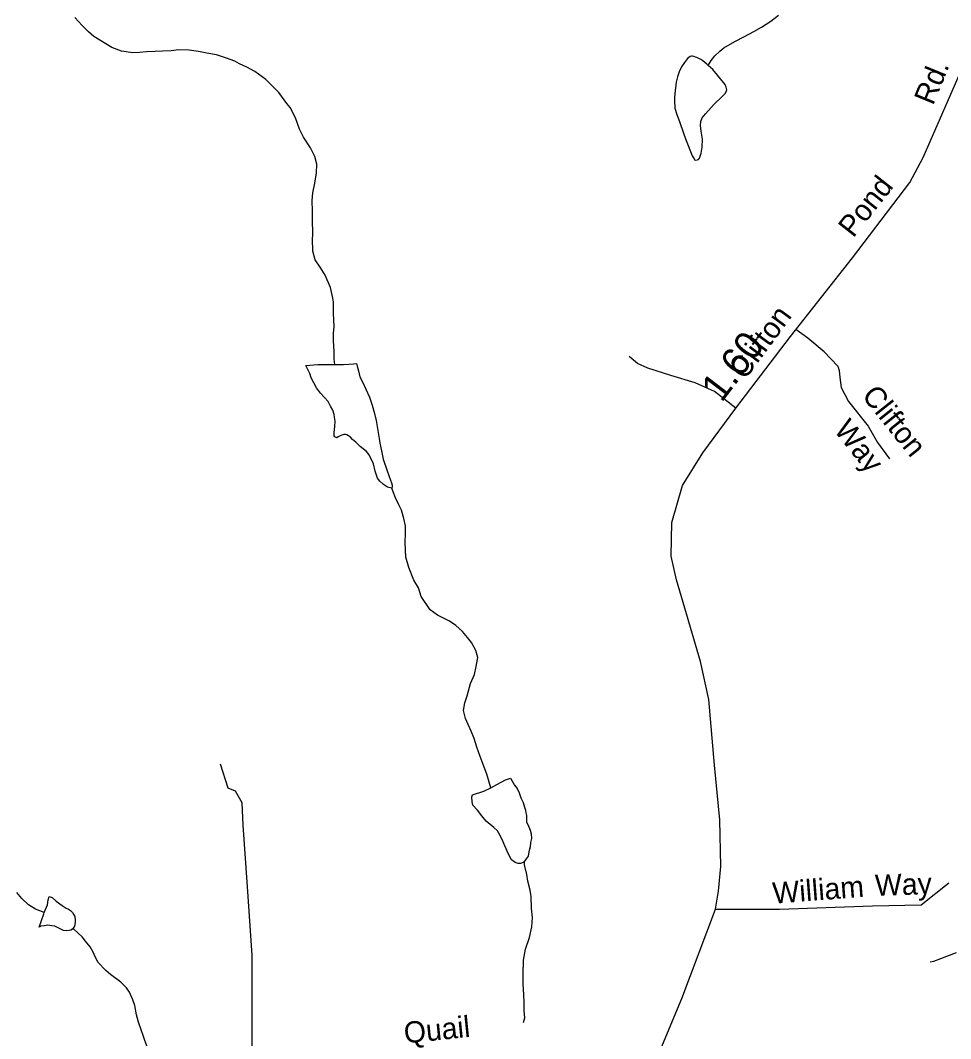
# Model space of a CAD drawing. Extents: x 2126262 to 2293712, y 749403 to 919119.
# Drawn here: x 2189866 to 2194027, y 811845 to 816398 of the extents above; entities that cross this region are included whole.
import ezdxf

# ---------------------------------------------------------------- set-up
doc = ezdxf.new("R2010")
doc.units = 0
for name, color, linetype in [('Exist Hydrographic Misc Water Feature', 7, 'Continuous'), ('Exist Road Non-System Type 51', 7, 'Continuous'), ('Exist Road Non-System Type 51 Label', 7, 'Continuous'), ('Exist Road Secondary Mileage Hundredths English Label', 7, 'Continuous'), ('Exist Road Secondary Type 51 Attributed', 7, 'Continuous'), ('Exist Road Secondary Type 51 Label', 7, 'Continuous')]:
    doc.layers.add(name, color=color, linetype=linetype)

msp = doc.modelspace()

# ---------------------------------------------------------------- linework, layer by layer
at = {"layer": 'Exist Hydrographic Misc Water Feature'}
for points in [[(2191271.9, 814859.4), (2191269.8, 814883.4), (2191269.6, 814919.4), (2191267.1, 814965.4), (2191266.7, 814999.4), (2191268.8, 815027.4), (2191266.3, 815089.3), (2191266.1, 815139.3), (2191261.8, 815163.3), (2191253.6, 815203.2), (2191229, 815259), (2191206.9, 815294.8), (2191184.9, 815326.7), (2191174.3, 815366.6), (2191172, 815420.6), (2191174.1, 815438.6), (2191173.2, 815512.6), (2191173.2, 815520.6), (2191173.2, 815544.5), (2191170.8, 815592.5), (2191174.7, 815626.5), (2191182.3, 815670.6), (2191190, 815716.6), (2191191.9, 815754.6), (2191183.5, 815788.5), (2191163.4, 815828.4), (2191133, 815876.1), (2191114.8, 815912), (2191096.3, 815961.9), (2191072.1, 816007.7), (2191058, 816025.6), (2191021.5, 816075.4), (2190963.3, 816132.9), (2190915.1, 816168.6), (2190878.8, 816188.3), (2190846.8, 816204.1), (2190824.9, 816216), (2190788.6, 816229.7), (2190742.6, 816243.4), (2190700.6, 816251.1), (2190662.7, 816258.8), (2190620.6, 816264.5), (2190574.5, 816266.2), (2190540.6, 816262), (2190502.5, 816259.7), (2190468.7, 816259.5), (2190430.5, 816257.2), (2190398.5, 816255), (2190368.6, 816252.8), (2190318.6, 816260.5), (2190274.5, 816276.2), (2190194.1, 816325.6), (2190170.1, 816347.4), (2190141.8, 816375.2), (2190109.6, 816411)], [(2192942, 816196.5), (2192956.2, 816218.6), (2192971.7, 816238.7), (2192993.9, 816260.8), (2193011.5, 816274.9), (2193061.4, 816303.3), (2193105.2, 816325.6), (2193147.1, 816347.9), (2193180.9, 816368.1), (2193222.7, 816394.4), (2193256.6, 816420.6)], [(2192942, 816196.5), (2192936.1, 816202.4), (2192918, 816216.3), (2192910, 816222.3), (2192900, 816228.2), (2192892, 816232.1), (2192885.8, 816234.1), (2192877.8, 816236.1), (2192871.9, 816238), (2192867.8, 816238), (2192861.8, 816235.9), (2192856.1, 816231.9), (2192850.2, 816227.9), (2192836, 816209.7), (2192822.3, 816189.7), (2192812.4, 816167.6), (2192804.6, 816145.5), (2192798.9, 816121.5), (2192793.1, 816069.5), (2192791.3, 816053.5), (2192791.3, 816039.5), (2192793.6, 816005.5), (2192801.8, 815977.6), (2192813.9, 815945.7), (2192832.3, 815893.8), (2192840.5, 815867.9), (2192852.6, 815838), (2192871.1, 815792.1), (2192879.1, 815778.2), (2192881.1, 815774.2), (2192887.1, 815772.2), (2192899.2, 815776.3), (2192903.1, 815782.3), (2192910.8, 815804.4), (2192914.7, 815830.4), (2192916.6, 815866.4), (2192910.2, 815902.3), (2192908.2, 815928.3), (2192909.8, 815946.4), (2192915.8, 815962.4), (2192929.5, 815980.5), (2192969.3, 816022.8), (2193005.2, 816057), (2193019.1, 816073), (2193024.9, 816087.1), (2193022.8, 816099.1), (2193018.9, 816111), (2192962.3, 816178.6), (2192942, 816196.5)], [(2191527.6, 814305.4), (2191507.5, 814311.2), (2191489.6, 814323.1), (2191473.2, 814337), (2191463.4, 814350.9), (2191453.1, 814382.8), (2191444.7, 814414.7), (2191426.5, 814454.6), (2191414.6, 814470.5), (2191386.3, 814492.3), (2191378.3, 814500.2), (2191366.4, 814512.2), (2191352, 814524.1), (2191342, 814534), (2191334, 814539.9), (2191326, 814543.9), (2191320.1, 814545.9), (2191312.1, 814545.8), (2191304.1, 814543.8), (2191296.1, 814539.7), (2191288.1, 814535.6), (2191282.1, 814531.6), (2191272.1, 814535.5), (2191270, 814539.5), (2191270, 814555.5), (2191271.9, 814581.5), (2191273.5, 814605.5), (2191271.7, 814623.5), (2191269.4, 814635.5), (2191263.3, 814655.5), (2191253, 814673.4), (2191243.2, 814693.3), (2191226.8, 814711.2), (2191208.9, 814731.1), (2191190.7, 814754.9), (2191166.3, 814798.8), (2191160.3, 814818.7), (2191152.1, 814836.6), (2191142.1, 814854.6), (2191195.8, 814858.9), (2191263.9, 814859.4), (2191271.9, 814859.4)], [(2191271.9, 814859.4), (2191311.8, 814859.7), (2191335.8, 814859.9), (2191355.7, 814862), (2191369.9, 814864.2), (2191371.7, 814852.1), (2191378.1, 814830.2), (2191384.2, 814804.2), (2191398.4, 814778.3), (2191410.5, 814748.5), (2191426.9, 814712.6), (2191439, 814676.6), (2191449.2, 814640.7), (2191457.6, 814608.8), (2191470.1, 814528.9), (2191474.3, 814507), (2191480.6, 814473), (2191488.8, 814435.1), (2191507.1, 814383.2), (2191521.4, 814341.3), (2191525.5, 814329.3), (2191529.6, 814319.4), (2191529.6, 814313.4), (2191527.6, 814305.4)], [(2191970.5, 812966.8), (2191952.2, 813026.7), (2191936, 813070.6), (2191921.9, 813106.5), (2191907.3, 813148.3), (2191895, 813186.2), (2191882.7, 813220.1), (2191868.8, 813250), (2191856.5, 813275.9), (2191848.3, 813311.9), (2191854, 813346), (2191863.8, 813377.9), (2191879.6, 813432.1), (2191897.3, 813472.2), (2191905.1, 813508.2), (2191912.7, 813548.2), (2191902.6, 813580.2), (2191884.4, 813616), (2191866.1, 813637.9), (2191843.8, 813665.7), (2191813.8, 813691.5), (2191785.5, 813711.3), (2191761.5, 813723.2), (2191731.4, 813738.9), (2191699.4, 813762.7), (2191658.8, 813822.4), (2191646.5, 813860.3), (2191626.4, 813894.2), (2191604, 813952), (2191589.9, 813997.9), (2191587.2, 814061.9), (2191589.1, 814103.9), (2191588.9, 814137.8), (2191580.5, 814169.8), (2191570.2, 814207.7), (2191558.1, 814231.6), (2191543.8, 814263.5), (2191533.7, 814289.4), (2191527.6, 814305.4)], [(2191970.5, 812966.8), (2191996.5, 812981), (2192036.3, 813001.3), (2192058.2, 813009.4), (2192076.5, 812977.5), (2192088.6, 812963.6), (2192096.8, 812943.7), (2192104.8, 812921.8), (2192115, 812899.9), (2192121.4, 812879.9), (2192125.3, 812865.9), (2192127.3, 812853.9), (2192129.6, 812841.9), (2192129.6, 812822), (2192129.6, 812814), (2192139.8, 812792.1), (2192145.8, 812776.1), (2192150.1, 812760.1), (2192152.2, 812740.1), (2192148.3, 812722.1), (2192146.2, 812702.1), (2192140.5, 812680.1), (2192136.8, 812660.1), (2192128.8, 812648), (2192120.8, 812638)], [(2192120.8, 812638), (2192114.8, 812631.9), (2192102.7, 812627.9), (2192092.9, 812627.8), (2192078.7, 812631.7), (2192062.8, 812643.6), (2192048.6, 812669.4), (2192032.4, 812707.3), (2192020.3, 812735.3), (2192006.2, 812763.1), (2192000, 812773.1), (2191983.8, 812789), (2191949.6, 812816.7), (2191929.5, 812840.6), (2191911.2, 812866.4), (2191889.3, 812888.3), (2191887, 812904.2), (2191885, 812926.2), (2191888.9, 812934.3), (2191938.9, 812950.6), (2191970.5, 812966.8)], [(2192115.9, 811916.2), (2192121.6, 811938.2), (2192119.5, 811970.2), (2192119.1, 812008.1), (2192117.1, 812040.1), (2192114.6, 812090.1), (2192114.2, 812132), (2192115.9, 812196), (2192125.5, 812244.1), (2192143.3, 812296.2), (2192152.8, 812344.3), (2192156.5, 812386.3), (2192152.4, 812428.2), (2192149.9, 812480.2), (2192145.8, 812508.2), (2192135.5, 812548.1), (2192131.2, 812578), (2192121, 812622), (2192120.8, 812638)], [(2189973.1, 812409.3), (2189933.1, 812423), (2189902.7, 812442.8), (2189872.8, 812470.5), (2189850.6, 812498.4)], [(2189973.1, 812409.3), (2189986.8, 812443.3), (2189990.9, 812465.4), (2189994.6, 812479.4), (2190008.5, 812475.5), (2190026.8, 812459.6), (2190052.8, 812439.8), (2190071.1, 812427.9), (2190081.1, 812424), (2190091, 812418.1), (2190099, 812408.2), (2190105.1, 812398.2), (2190109.2, 812390.2), (2190111.3, 812374.2), (2190111.3, 812364.2), (2190107.6, 812348.2), (2190101.6, 812338.2)], [(2190101.6, 812338.2), (2190099.6, 812334.2), (2190091.6, 812330.1), (2190083.6, 812328), (2190073.5, 812326), (2190059.6, 812327.9), (2190035.6, 812339.7), (2190019.6, 812347.6), (2190007.5, 812349.5), (2189989.5, 812351.4), (2189973.5, 812349.3), (2189957.5, 812347.1), (2189949.5, 812343.2), (2189971, 812403.3), (2189973.1, 812409.3)], [(2190455.8, 811720.8), (2190445.5, 811754.7), (2190439.4, 811778.6), (2190431.2, 811812.6), (2190422.7, 811836.5), (2190416.8, 811854.5), (2190406.5, 811884.4), (2190394.2, 811918.3), (2190386, 811950.3), (2190377.8, 811992.2), (2190369.6, 812018.1), (2190353.6, 812052), (2190341.3, 812071.9), (2190315.1, 812097.7), (2190268.7, 812131.4), (2190248.9, 812149.2), (2190214.6, 812185), (2190200.3, 812210.9), (2190192.3, 812230.8), (2190178.1, 812254.7), (2190158, 812280.6), (2190141.8, 812300.4), (2190105.5, 812334.2), (2190101.6, 812338.2)], [(2193935.3, 812188.5), (2193951.3, 812190.7), (2193983.3, 812202.9), (2194009.1, 812213), (2194053, 812229.4)]]:
    msp.add_lwpolyline(points, dxfattribs=at)
at = {"layer": 'Exist Road Non-System Type 51'}
for points in [[(2193521.7, 814851.5), (2193460.2, 814915.2), (2193387.7, 814976.8), (2193334.8, 815015.2)], [(2193065.9, 814664.3), (2192970, 814737.9), (2192883.5, 814777), (2192774.7, 814810.6), (2192672.1, 814842), (2192626.1, 814864.3), (2192588.4, 814895)], [(2193521.7, 814851.5), (2193528.3, 814831.7), (2193530.5, 814800.9), (2193537.1, 814756.9), (2193570.1, 814693.1), (2193658, 814583.2), (2193699.7, 814510.6), (2193752.5, 814438)], [(2190978.4, 810869.2), (2190947.4, 811096.6), (2190924.8, 811477.4), (2190913.7, 811614.2), (2190902.5, 811826.5), (2190902.5, 812217.6), (2190882.3, 812522.7), (2190862, 812798.5), (2190857.8, 812899.1), (2190828.5, 812950.7), (2190795, 812964.7), (2190761.6, 813072.2)], [(2192975.2, 812422.9), (2193261.6, 812424), (2193677.4, 812438), (2193895.1, 812443.5), (2194017.9, 812541.3)]]:
    msp.add_lwpolyline(points, dxfattribs=at)
at = {"layer": 'Exist Road Secondary Type 51 Attributed'}
msp.add_lwpolyline([(2192604.1, 811494.3), (2192823.9, 812024.3), (2192975.2, 812422.9), (2192987.8, 812503.9), (2192999, 812614.3), (2192994.1, 812823), (2192970.4, 813067.4), (2192944.6, 813361.4), (2192908.3, 813531.7), (2192800.1, 813895.5), (2192776.4, 814001.7), (2192779.2, 814152.5), (2192828, 814317.3), (2192918, 814464.6), (2193065.9, 814664.3), (2193310.8, 814984.8), (2193587.8, 815336), (2193843.8, 815673.2), (2193903.8, 815784.9), (2194090.1, 816211.6)], dxfattribs=at)

# ---------------------------------------------------------------- texts
at = {"layer": 'Exist Road Non-System Type 51 Label'}
for s, rotation, p in [('Clifton', 308.6388, (2193625.7, 814719)), ('Way', 308.6388, (2193501.1, 814565.1)), ('William', 4.4031, (2193233.7, 812447.7)), ('Way', 1.9494, (2193689.8, 812482.7)), ('Quail', 5.7712, (2191586.1, 811822.9))]:
    msp.add_text(s, height=95, rotation=rotation, dxfattribs=at).set_placement(p)
at = {"layer": 'Exist Road Secondary Mileage Hundredths English Label'}
msp.add_text('1.60', height=125, rotation=52.6183, dxfattribs=at).set_placement((2193001.7, 814685.8))
at = {"layer": 'Exist Road Secondary Type 51 Label'}
for s, rotation, p in [('Rd.', 67.6815, (2193947.7, 816014.3)), ('Pond', 51.7515, (2193591, 815422)), ('Clifton', 53.66, (2193106.7, 814786.7))]:
    msp.add_text(s, height=95, rotation=rotation, dxfattribs=at).set_placement(p)

doc.saveas('drawing.dxf')
